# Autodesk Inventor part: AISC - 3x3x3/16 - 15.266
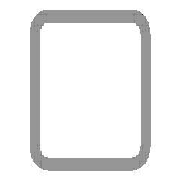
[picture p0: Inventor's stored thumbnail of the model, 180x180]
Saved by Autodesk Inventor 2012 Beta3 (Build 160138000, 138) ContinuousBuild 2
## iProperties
_CCFamilyMember: 9
_CCFamilyDisplayName: ANSI AISC (Square) - Tube
_FrameMemberDoc: Frame Member File
_Version: 15.0.0
_GetPNFromCC: 1
Created: 2011-01
Part Number: AISC - 3x3x3/16 - 15.266
Material: Steel, Mild
Description: Tube
Document SubType Name: Modeling
Standard: ANSI
Designer: Beta-8540w
Standards Organization: ANSI
Language: en-US
Size Designation: 3x3x3/16
Categories: <MemberInstance><Categories><Category DisplayName="Structural Shapes" InternalName="089c4875-fa83-4c05-b084-43b9cc11f5ed" Mnemonic="GRDR"><CategoryParameter Dis
Stock Number: 3x3x3/16
Density: 7.86 g/cm^3
IsCustomPart: 1
G_L: 15.266 in
G_W: 3.000 in
G_H: 3.000 in
+97117C38-DCE9-4757-BAD2-BD9438CA5631+CUTDETAIL1: Cut
+82DD3A4A-9495-4CA2-B707-475D0CBCAB53+CUTDETAIL2: Cut
Author: Beta-8540w
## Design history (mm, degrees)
node "Start plane"
node "End plane"
sketch "Sketch"
  geometry: L1 (-38.1, -28.575)-(-38.1, 28.575); L2 (-28.575, 38.1)-(28.575, 38.1); L3 (38.1, 28.575)-(38.1, -28.575); L4 (28.575, -38.1)-(-28.575, -38.1); L5 (-28.575, 33.337)-(28.575, 33.338); L6 (33.338, 28.575)-(33.338, -28.575); L7 (28.575, -33.337)-(-28.575, -33.338); L8 (-33.338, -28.575)-(-33.338, 28.575); L9 (0, 56.102)-(0, -56.102) reference; L10 (-56.102, 0)-(56.102, 0) reference; A1 r 9.525 centre (-28.575, -28.575) between (-38.1, -28.575) and (-28.575, -38.1); A2 r 9.525 centre (-28.575, 28.575) between (-28.575, 38.1) and (-38.1, 28.575); A3 r 9.525 centre (28.575, 28.575) between (38.1, 28.575) and (28.575, 38.1); A4 r 9.525 centre (28.575, -28.575) between (28.575, -38.1) and (38.1, -28.575); A5 r 4.763 centre (-28.575, 28.575) between (-28.575, 33.337) and (-33.338, 28.575); A6 r 4.763 centre (28.575, 28.575) between (33.338, 28.575) and (28.575, 33.338); A7 r 4.763 centre (28.575, -28.575) between (28.575, -33.337) and (33.338, -28.575); A8 r 4.763 centre (-28.575, -28.575) between (-33.338, -28.575) and (-28.575, -33.338)
  constraints: 16 end point, 16 point on circle, 8 centre point, 8 tangent, 4 parallel, 3 equal radius, 2 perpendicular, 7 other
  dimensions: "d10" = 76.2 distance between parallel lines of L2 L4 (= G_H); "d11" = 76.2 distance between parallel lines of L1 L3 (= G_W); "d12" = 4.7625 distance between parallel lines of L3 L6 (= G_T); "d15" = 38.1 distance between parallel lines of L2 L10 (= 0.5 x d10); "d16" = 38.1 distance between parallel lines of L9 L3 (= 0.5 x d11); "d17" = 9.525 radius of A1 (= G_IR)
extrude "Body" new body sketch "Sketch" stored distance "d3" = 387.75605 (= G_L); taper "d4" = 0 deg
node "Driven Length"
  sketch "Sketch3"
    geometry: L1 (0, 0)-(10, 0) reference
    constraints: 2 end point, 1 horizontal
  workplane "Work Plane3"
  sketch "Sketch4"
    geometry: L1 (-2, 31.109)-(12, 31.109) reference; L2 (-2, 418.865)-(12, 418.865) reference
    dimensions: "d19" = 387.75605 distance between parallel lines of L1 L2 (derived)
workplane "Work Plane4"
split "Split1"
workplane "Work Plane5"
split "Split2"
body "Solid1"
other parameters: "G_W" = 76.2 [user parameter; used in 1 equation term], "G_H" = 76.2 [user parameter; used in 1 equation term], "G_T" = 4.7625 [user parameter; used in 1 equation term], "G_IR" = 9.525 [user parameter; used in 1 equation term], "G_L" = 387.75605 (= d19) [user parameter; used in 1 equation term], "G_OFFSET_START" = -31.10852 [user parameter; used in 1 equation term], "G_OFFSET_END" = -31.10852 [user parameter; used in 1 equation term], "d13" = 31.10852 (= -G_OFFSET_START), "d14" = 418.86457 (= G_OFFSET_END + B_L), "B_L" = 449.97309 [user parameter; used in 1 equation term], "d18" = 90 deg
